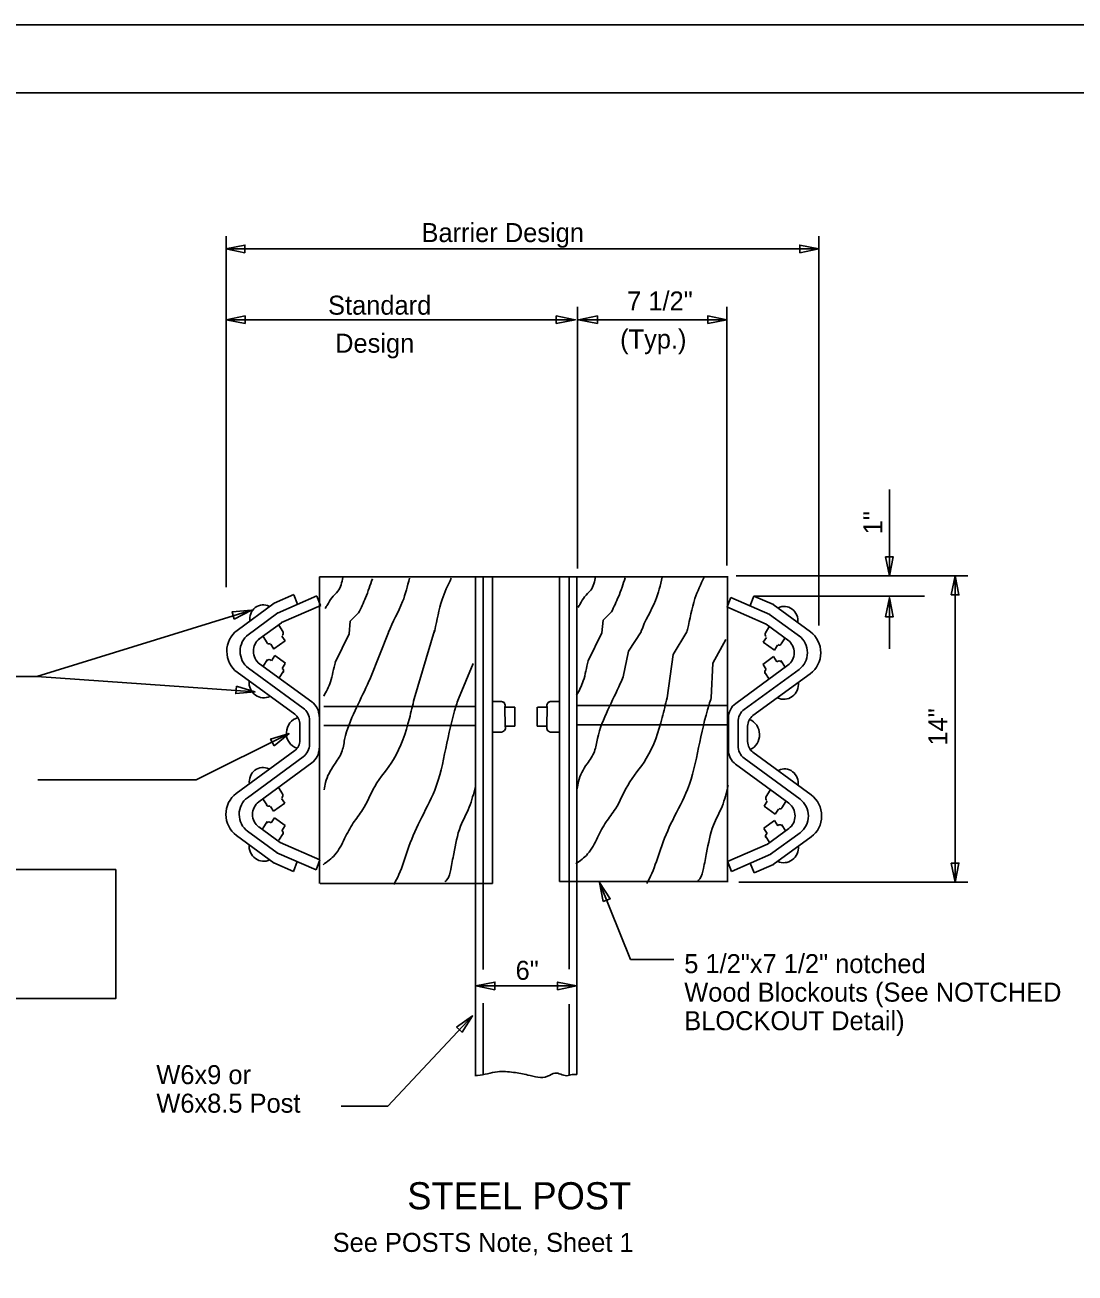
# Model space of a CAD drawing. Extents: x -0.7 to 89.2, y -3.6 to 22.
# Drawn here: x 11.14 to 18.88, y 12.81 to 22 of the extents above; entities that cross this region are included whole.
import ezdxf

# ---------------------------------------------------------------- set-up
doc = ezdxf.new("R2010")
doc.units = 0
for name, color, linetype in [('Default', 7, 'Continuous'), ('SH_Border', 7, 'Continuous'), ('ST_Text', 7, 'Continuous')]:
    doc.layers.add(name, color=color, linetype=linetype)

msp = doc.modelspace()

# ---------------------------------------------------------------- linework, layer by layer
at = {"layer": 'Default'}
for p, q in [((12.6239, 20.446), (12.624, 17.8618)), ((16.9876, 20.446), (16.9876, 17.5801)), ((12.6219, 20.3515), (16.9876, 20.3515)), ((15.2122, 19.924), (15.2122, 17.9976)), ((16.311, 19.924), (16.311, 18.0218)), ((12.6235, 19.8295), (13.2017, 19.8295)), ((13.2017, 19.8295), (15.1951, 19.8295)), ((15.2179, 19.8295), (15.5856, 19.8295)), ((15.5856, 19.8295), (16.311, 19.8295)), ((17.5079, 18.5801), (17.5079, 17.9446)), ((13.3103, 17.937), (16.3213, 17.937)), ((13.3103, 17.937), (13.3103, 15.6805)), ((14.459, 15.6806), (14.459, 17.9298)), ((14.5157, 15.6806), (14.5157, 17.9298)), ((14.5865, 15.6806), (14.5865, 17.9298)), ((15.0795, 15.695), (15.0795, 17.9345)), ((15.1503, 15.695), (15.1503, 17.9345)), ((15.207, 15.695), (15.207, 17.9345)), ((16.317, 17.937), (16.317, 15.6948)), ((16.3805, 17.9446), (18.0865, 17.9446)), ((17.992, 17.9446), (17.992, 17.239)), ((12.978, 17.7431), (12.705, 17.5431)), ((12.9777, 17.7435), (13.1216, 17.8063)), ((13.0025, 17.6705), (13.2919, 17.7968)), ((13.1491, 17.7361), (13.1221, 17.8055)), ((13.318, 17.7266), (13.291, 17.7958)), ((16.3132, 17.7158), (16.3402, 17.7851)), ((16.6289, 17.6596), (16.3394, 17.786)), ((16.4822, 17.7255), (16.5092, 17.7946)), ((16.5096, 17.7955), (17.7678, 17.7955)), ((16.6536, 17.7326), (16.5096, 17.7955)), ((17.5079, 17.7827), (17.5079, 17.4077)), ((13.005, 17.672), (12.775, 17.5033)), ((13.0316, 17.6), (13.3212, 17.7261)), ((13.5996, 17.6713), (13.5373, 17.6106)), ((15.4619, 17.6785), (15.3995, 17.6178)), ((16.5996, 17.5891), (16.3101, 17.7155)), ((16.6263, 17.6611), (16.8564, 17.4925)), ((16.6533, 17.7323), (16.9262, 17.5323)), ((13.0308, 17.5995), (12.8641, 17.4773)), ((13.0422, 17.5348), (13.012, 17.5821)), ((13.5291, 17.5166), (13.5373, 17.6106)), ((15.3913, 17.5238), (15.3995, 17.6178)), ((16.5949, 17.5261), (16.625, 17.5735)), ((16.6005, 17.5886), (16.7672, 17.4665)), ((12.9265, 17.4523), (12.8973, 17.498)), ((12.975, 17.4063), (13.0575, 17.4648)), ((13.0574, 17.4648), (13.0347, 17.5003)), ((13.5291, 17.5166), (13.427, 17.3058)), ((13.8187, 17.5285), (13.6866, 17.1926)), ((14.159, 17.5416), (14.0084, 17.0396)), ((15.3913, 17.5238), (15.2903, 17.3176)), ((16.5796, 17.4561), (16.6023, 17.4916)), ((16.7106, 17.4436), (16.7397, 17.4893)), ((12.9751, 17.4058), (12.952, 17.4421)), ((16.6621, 17.3976), (16.5795, 17.4563)), ((16.6619, 17.3973), (16.685, 17.4335)), ((13.255, 17.0161), (12.8703, 17.2965)), ((12.8968, 17.2796), (12.9285, 17.3296)), ((12.9567, 17.32), (12.9814, 17.3586)), ((13.0599, 17.301), (12.9812, 17.3585)), ((13.0357, 17.2625), (13.0595, 17.3)), ((14.3341, 17.0396), (14.4425, 17.2985)), ((16.3763, 17.0055), (16.761, 17.2858)), ((16.5772, 17.2923), (16.6559, 17.3498)), ((16.6014, 17.2538), (16.5775, 17.2915)), ((16.6803, 17.3113), (16.6556, 17.35)), ((16.7403, 17.271), (16.7085, 17.321)), ((12.8361, 17.0905), (11.2294, 17.2028)), ((13.1286, 16.9261), (12.7055, 17.2346)), ((13.1918, 16.9711), (12.7879, 17.2656)), ((13.0148, 17.1936), (13.0458, 17.2421)), ((16.4395, 16.9605), (16.8434, 17.2548)), ((16.5027, 16.9155), (16.9259, 17.2238)), ((16.6222, 17.185), (16.5913, 17.2336)), ((17.992, 17.239), (17.992, 15.69)), ((14.4605, 16.7855), (14.4605, 17.018)), ((14.585, 17.0193), (14.6535, 17.0193)), ((15.0795, 17.0193), (15.0112, 17.0193)), ((14.4545, 16.982), (13.3425, 16.982)), ((14.6773, 16.9785), (14.75, 16.9785)), ((14.6773, 16.9785), (14.6783, 16.8383)), ((14.75, 16.8383), (14.75, 16.9785)), ((14.9146, 16.8383), (14.9146, 16.9775)), ((14.9874, 16.9785), (14.9156, 16.9785)), ((14.9874, 16.9785), (14.9863, 16.8383)), ((16.3167, 16.989), (15.2048, 16.989)), ((13.167, 16.7346), (13.167, 16.849)), ((13.2378, 16.7053), (13.2378, 16.8785)), ((14.4545, 16.8418), (13.3422, 16.8418)), ((14.6783, 16.8383), (14.75, 16.8383)), ((14.9863, 16.8383), (14.9146, 16.8383)), ((16.3167, 16.8488), (15.2044, 16.8488)), ((16.3227, 16.6648), (16.3227, 16.8973)), ((16.3935, 16.6945), (16.3935, 16.8676)), ((16.4643, 16.7238), (16.4643, 16.8383)), ((13.0872, 16.7838), (12.402, 16.442)), ((13.2378, 16.7865), (13.2378, 16.7973)), ((14.585, 16.7948), (14.6446, 16.7948)), ((15.0795, 16.7948), (15.02, 16.7948)), ((16.3935, 16.7758), (16.3935, 16.7865)), ((13.1288, 16.6575), (12.6985, 16.3421)), ((16.5025, 16.6468), (16.9329, 16.3313)), ((13.192, 16.6128), (12.7809, 16.3113)), ((13.2553, 16.5678), (12.8635, 16.2806)), ((16.376, 16.557), (16.7678, 16.2698)), ((16.4393, 16.602), (16.8504, 16.3005)), ((11.237, 16.442), (12.402, 16.442)), ((13.0399, 16.3401), (13.0097, 16.3875)), ((16.6005, 16.3196), (16.6306, 16.367)), ((12.924, 16.2575), (12.895, 16.3031)), ((12.9726, 16.2115), (13.0551, 16.2701)), ((13.055, 16.27), (13.0324, 16.3055)), ((16.5853, 16.2495), (16.608, 16.285)), ((16.7163, 16.237), (16.7454, 16.2826)), ((12.9728, 16.2111), (12.9496, 16.2475)), ((16.6678, 16.191), (16.5852, 16.2496)), ((16.6675, 16.1906), (16.6907, 16.227)), ((13.0211, 15.9808), (12.8637, 16.0955)), ((12.8944, 16.085), (12.9261, 16.135)), ((12.9544, 16.1253), (12.979, 16.164)), ((13.0575, 16.1063), (12.9788, 16.1638)), ((13.0333, 16.0678), (13.0572, 16.1053)), ((16.5829, 16.0858), (16.6615, 16.1433)), ((16.607, 16.0473), (16.5831, 16.0848)), ((16.6101, 15.97), (16.7675, 16.0846)), ((16.686, 16.1048), (16.6613, 16.1435)), ((16.746, 16.0645), (16.7142, 16.1145)), ((12.9783, 15.8298), (12.6988, 16.0335)), ((12.999, 15.9058), (12.7813, 16.0645)), ((13.0125, 15.9988), (13.0435, 16.0475)), ((16.6279, 15.9783), (16.597, 16.027)), ((16.6322, 15.895), (16.85, 16.0536)), ((16.653, 15.819), (16.9325, 16.0226)), ((13.2869, 15.78), (12.9975, 15.9063)), ((13.0211, 15.9811), (13.3149, 15.8531)), ((16.6101, 15.9703), (16.3165, 15.8423)), ((12.976, 15.8306), (13.12, 15.7678)), ((13.119, 15.7681), (13.1474, 15.8408)), ((13.286, 15.78), (13.3148, 15.8536)), ((16.3452, 15.7691), (16.3165, 15.8428)), ((16.3444, 15.7691), (16.6339, 15.8955)), ((16.5122, 15.7575), (16.4839, 15.83)), ((16.6553, 15.8198), (16.5114, 15.7571)), ((13.3153, 15.6806), (14.5865, 15.6806)), ((14.459, 14.2685), (14.459, 15.6806)), ((14.5157, 15.047), (14.5157, 15.6806)), ((16.3213, 15.695), (15.0795, 15.695)), ((15.1503, 15.0491), (15.1503, 15.695)), ((15.207, 14.2731), (15.207, 15.695)), ((15.6005, 15.1191), (15.3735, 15.687)), ((16.3984, 15.69), (18.0865, 15.69)), ((15.6005, 15.1191), (15.9214, 15.1191)), ((14.459, 14.9256), (15.2042, 14.9256)), ((14.4627, 14.9256), (14.6502, 14.9256)), ((14.5157, 14.2685), (14.5157, 14.7995)), ((13.814, 14.0393), (14.4383, 14.7041)), ((15.1503, 14.2731), (15.1503, 14.7908)), ((13.814, 14.0393), (13.4712, 14.0393))]:
    msp.add_line(p, q, dxfattribs=at)
for points in [[(12.7619, 20.3235), (12.6219, 20.3515), (12.7619, 20.3795)], [(16.8476, 20.3235), (16.9876, 20.3515), (16.8476, 20.3795)], [(12.7635, 19.8015), (12.6235, 19.8295), (12.7635, 19.8575)], [(15.0551, 19.8015), (15.1951, 19.8295), (15.0551, 19.8575)], [(15.3579, 19.8015), (15.2179, 19.8295), (15.3579, 19.8575)], [(16.171, 19.8015), (16.311, 19.8295), (16.171, 19.8575)], [(17.4799, 18.0846), (17.5079, 17.9446), (17.5359, 18.0846)], [(17.964, 17.8046), (17.992, 17.9446), (18.02, 17.8046)], [(17.4799, 17.6427), (17.5079, 17.7827), (17.5359, 17.6427)], [(12.6833, 17.6266), (12.8102, 17.6921), (12.6679, 17.6805)], [(12.6998, 17.1329), (12.8361, 17.0905), (12.6939, 17.0772)], [(12.9768, 16.6933), (13.0872, 16.7838), (12.9505, 16.7428)], [(17.964, 15.83), (17.992, 15.69), (18.02, 15.83)], [(9.0255, 15.7816), (11.8104, 15.7816), (11.8104, 14.8328), (9.0255, 14.8328)], [(15.3999, 15.5467), (15.3735, 15.687), (15.4519, 15.5676)], [(14.6027, 14.8976), (14.4627, 14.9256), (14.6027, 14.9536)], [(15.0642, 14.8976), (15.2042, 14.9256), (15.0642, 14.9536)], [(14.3209, 14.6229), (14.4383, 14.7041), (14.3612, 14.584)]]:
    msp.add_lwpolyline(points, close=True, dxfattribs=at)
for points in [[(12.8102, 17.6921), (11.2294, 17.2028), (10.9787, 17.2028)], [(15.5488, 17.1998), (15.5879, 17.3888), (15.68, 17.5328)], [(15.8705, 17.0466), (15.9155, 17.3663), (16.017, 17.5328)], [(16.1964, 17.0466), (16.2068, 17.302), (16.3048, 17.4755)]]:
    msp.add_lwpolyline(points, dxfattribs=at)
for centre, major_axis, start_param, end_param in [((12.8977, 17.6242), (0, -0.1065), 2.687211, 4.851441), ((16.7336, 17.6134), (0, -0.1065), 1.431744, 3.595974), ((12.8058, 17.389), (0, -0.1875), 3.747084, 5.680264), ((12.8682, 17.3891), (0, -0.15), 3.747137, 5.680324), ((12.9306, 17.3892), (0, -0.1125), 3.747102, 5.680297), ((13.0263, 17.5224), (0, 0.0198), 3.70437, 5.352473), ((16.6107, 17.5138), (0, 0.0198), 0.930712, 2.578815), ((16.7007, 17.3784), (0, -0.1125), 0.602888, 2.536083), ((16.7631, 17.3783), (0, -0.15), 0.602861, 2.536048), ((16.8254, 17.3782), (0, -0.1875), 0.602921, 2.536101), ((12.9393, 17.4629), (0, -0.0195), 5.247458, 6.879592), ((16.6978, 17.4543), (0, -0.0195), 5.686779, 7.318912), ((12.941, 17.3064), (0, 0.021), 5.452301, 7.118326), ((16.6961, 17.2978), (0, 0.021), 5.448045, 7.11407), ((13.0266, 17.2439), (0, 0.021), 4.196406, 5.73538), ((16.6104, 17.2353), (0, 0.021), 0.547805, 2.086779), ((12.9009, 17.1616), (0, -0.115), 4.640651, 6.714317), ((16.7304, 17.1508), (0, -0.115), 5.852054, 7.925719), ((13.1847, 16.9081), (0, 0.1312), 4.712389, 5.680267), ((14.6518, 16.9898), (0, -0.0298), 2.729343, 3.43401), ((14.6507, 16.989), (0, 0.03), 4.35702, 6.237266), ((15.0139, 16.989), (0, 0.03), 0.045919, 1.926166), ((15.0128, 16.9898), (0, -0.0298), 2.849176, 3.553842), ((16.4466, 16.8973), (0, 0.1312), 0.602918, 1.570796), ((13.0784, 16.849), (0, 0.0937), 4.712389, 5.680377), ((13.1315, 16.8786), (0, 0.1125), 4.712389, 5.68034), ((14.6518, 16.9898), (0, -0.0298), 1.431351, 1.439211), ((15.0128, 16.9898), (0, -0.0298), 4.843974, 4.851834), ((16.4997, 16.8678), (0, 0.1125), 0.602846, 1.570796), ((16.5529, 16.8382), (0, 0.0937), 0.602808, 1.570796), ((13.1777, 16.7864), (0, -0.1171), 3.363241, 5.976631), ((14.6496, 16.8266), (0, -0.0326), 6.093782, 8.224205), ((15.015, 16.8266), (0, -0.0326), 4.342165, 6.472589), ((16.4389, 16.7752), (0, -0.1192), 0.40519, 2.779828), ((13.0784, 16.7346), (0, -0.0937), 0.605563, 1.570796), ((16.5529, 16.7238), (0, -0.0937), 4.712389, 5.677623), ((13.1315, 16.7052), (0, -0.1125), 0.605651, 1.570796), ((13.1847, 16.6756), (0, -0.1312), 0.605566, 1.570796), ((16.4466, 16.6648), (0, -0.1312), 4.712389, 5.677619), ((16.4997, 16.6944), (0, -0.1125), 4.712389, 5.677535), ((12.8946, 16.4272), (0, -0.1065), 2.687211, 4.851441), ((16.7366, 16.4164), (0, -0.1065), 1.431744, 3.595974), ((12.7992, 16.1879), (0, -0.1875), 3.747091, 5.68028), ((12.8615, 16.188), (0, -0.15), 3.747115, 5.680355), ((12.924, 16.1881), (0, -0.1125), 3.747102, 5.680258), ((13.024, 16.3276), (0, 0.0198), 3.70437, 5.352473), ((16.6164, 16.3071), (0, 0.0198), 0.930712, 2.578815), ((16.7073, 16.1773), (0, -0.1125), 0.602927, 2.536083), ((16.7697, 16.1772), (0, -0.15), 0.602831, 2.53607), ((16.8321, 16.1771), (0, -0.1875), 0.602905, 2.536094), ((12.9369, 16.2682), (0, -0.0195), 5.247458, 6.879592), ((16.7034, 16.2477), (0, -0.0195), 5.686779, 7.318912), ((12.9386, 16.1117), (0, 0.021), 5.452301, 7.118326), ((16.7018, 16.0912), (0, 0.021), 5.448045, 7.11407), ((13.0243, 16.0492), (0, 0.021), 4.196406, 5.73538), ((16.6161, 16.0287), (0, 0.021), 0.547805, 2.086779), ((12.9009, 15.9583), (0, -0.115), 4.640651, 6.714317), ((16.7304, 15.9475), (0, -0.115), 5.852054, 7.925719)]:
    msp.add_ellipse(centre, major_axis=major_axis, ratio=0.944544, start_param=start_param, end_param=end_param, dxfattribs=at)
for points in [[(13.4828, 17.9326), (13.4465, 17.8318), (13.401, 17.7836), (13.3693, 17.7308), (13.353, 17.705)], [(13.7008, 17.9231), (13.6508, 17.7836), (13.5996, 17.6713)], [(13.9732, 17.928), (13.9233, 17.7548), (13.8189, 17.5288), (13.8177, 17.5256)], [(14.282, 17.928), (14.2139, 17.7693), (14.1594, 17.5433), (14.1547, 17.5256)], [(15.345, 17.9398), (15.3087, 17.839), (15.2632, 17.7908), (15.2315, 17.738), (15.2153, 17.7121)], [(15.563, 17.9303), (15.513, 17.7908), (15.4619, 17.6785)], [(15.8355, 17.9351), (15.7855, 17.762), (15.681, 17.536), (15.68, 17.5328)], [(16.1442, 17.9351), (16.0761, 17.7765), (16.0216, 17.5505), (16.017, 17.5328)], [(13.4281, 17.3105), (13.4102, 17.2356), (13.392, 17.1635), (13.342, 17.0578)], [(15.2903, 17.3176), (15.2724, 17.2428), (15.2542, 17.1706), (15.2042, 17.0648)], [(13.6866, 17.1926), (13.6645, 17.1443), (13.5735, 16.952), (13.4965, 16.7405), (13.4738, 16.6443), (13.4193, 16.553), (13.3557, 16.4233), (13.3465, 16.3703)], [(15.5488, 17.1998), (15.5266, 17.1515), (15.4358, 16.9591), (15.3586, 16.7476), (15.336, 16.6515), (15.2815, 16.5601), (15.2179, 16.4303), (15.2088, 16.3775)], [(14.0084, 17.0396), (13.9732, 16.8943), (13.8552, 16.5915), (13.719, 16.3943), (13.628, 16.2213), (13.56, 16.1251), (13.4965, 16.0098), (13.4238, 15.8896), (13.3375, 15.8175)], [(14.3341, 17.0396), (14.3183, 16.9905), (14.241, 16.6731), (14.1594, 16.3655), (14.0504, 16.1396), (13.9595, 15.9231), (13.896, 15.7453), (13.8597, 15.6733)], [(15.8705, 17.0466), (15.8355, 16.9015), (15.7174, 16.5986), (15.5811, 16.4015), (15.4903, 16.2285), (15.4222, 16.1323), (15.3586, 16.017), (15.286, 15.8968), (15.1997, 15.8246)], [(16.1964, 17.0466), (16.1805, 16.9976), (16.1033, 16.6803), (16.0216, 16.3726), (15.9126, 16.1468), (15.8218, 15.9303), (15.7582, 15.7525), (15.722, 15.6805)], [(14.459, 16.3943), (14.4137, 16.2406), (14.35, 16.1011), (14.3002, 15.8991), (14.2775, 15.7838), (14.2502, 15.7068), (14.2365, 15.6925)], [(16.3213, 16.4015), (16.276, 16.2476), (16.2123, 16.1083), (16.1624, 15.9063), (16.1396, 15.791), (16.1125, 15.714), (16.0988, 15.6996)], [(14.4561, 14.2661), (14.4748, 14.2668), (14.623, 14.2936), (14.741, 14.2888), (14.8455, 14.2696), (14.9908, 14.26), (15.0453, 14.284), (15.1316, 14.2648), (15.1715, 14.2731), (15.207, 14.2731)]]:
    msp.add_spline(points, degree=3, dxfattribs=at)
at = {"layer": 'SH_Border'}
msp.add_lwpolyline([(1.5, 21.5), (33.5, 21.5), (33.5, 0.5), (1.5, 0.5)], close=True, dxfattribs=at)
at = {"layer": 'ST_Text'}
msp.add_lwpolyline([(0, 0), (34, 0), (34, 22), (0, 22)], close=True, dxfattribs=at)

# ---------------------------------------------------------------- texts
at = {"layer": 'Default'}
for s, height, p in [('Barrier Design', 0.14, (14.0624, 20.4017)), (' 7 1/2"', 0.14, (15.5251, 19.8981)), ('Standard', 0.14, (13.3743, 19.8671)), ('(Typ.)', 0.14, (15.5251, 19.6181)), (' Design', 0.14, (13.3743, 19.5871)), ('5 1/2"x7 1/2" notched', 0.14, (15.9975, 15.0196)), ('6" ', 0.14, (14.7553, 14.9705)), ('Wood Blockouts (See NOTCHED', 0.14, (15.9975, 14.8096)), ('BLOCKOUT Detail)', 0.14, (15.9975, 14.5996)), ('W6x9 or', 0.14, (12.1097, 14.2023)), ('W6x8.5 Post', 0.14, (12.1097, 13.9923)), ('STEEL POST', 0.2, (13.9575, 13.2806)), ('See POSTS Note, Sheet 1', 0.14, (13.4083, 12.9673))]:
    msp.add_text(s, height=height, dxfattribs=at).set_placement(p)
for s, p in [('1" ', (17.4568, 18.2502)), ('14" ', (17.9345, 16.6948))]:
    msp.add_text(s, height=0.14, rotation=90, dxfattribs=at).set_placement(p)

doc.saveas('drawing.dxf')
